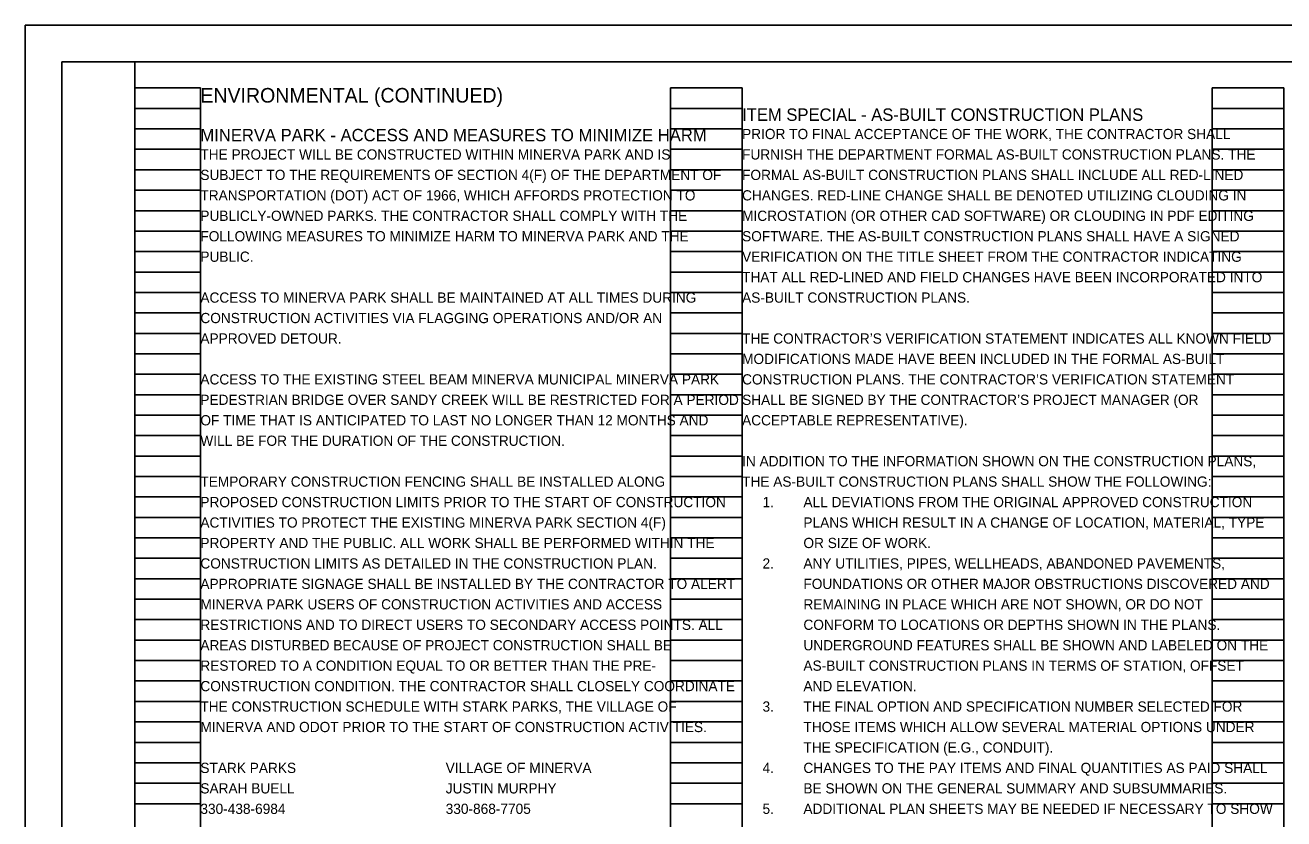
# Model space of a CAD drawing. Extents: x 0 to 34, y 0 to 22.
# Drawn here: x 0 to 17.24, y 11.13 to 22 of the extents above; entities that cross this region are included whole.
import ezdxf

# ---------------------------------------------------------------- set-up
doc = ezdxf.new("R2010")
doc.units = 0
for name, color, linetype in [('SH_Border', 7, 'Continuous'), ('SH_Cut_Line', 7, 'Continuous'), ('SH_Data', 7, 'Continuous'), ('SH_Text', 7, 'Continuous')]:
    doc.layers.add(name, color=color, linetype=linetype)

msp = doc.modelspace()

# ---------------------------------------------------------------- linework, layer by layer
at = {"layer": 'SH_Border'}
for points in [[(0.5, 21.5), (1.5, 21.5), (1.5, 0.5), (0.5, 0.5)], [(1.5, 21.5), (33.5, 21.5), (33.5, 0.5), (1.5, 0.5)]]:
    msp.add_lwpolyline(points, close=True, dxfattribs=at)
at = {"layer": 'SH_Cut_Line'}
msp.add_lwpolyline([(0, 0), (34, 0), (34, 22), (0, 22)], close=True, dxfattribs=at)
at = {"layer": 'SH_Data'}
for p, q in [((1.5, 0.98), (1.5, 21.14)), ((1.5, 21.14), (2.4, 21.14)), ((2.4, 0.98), (2.4, 21.14)), ((8.84, 0.98), (8.84, 21.14)), ((8.84, 21.14), (9.82, 21.14)), ((9.82, 0.98), (9.82, 21.14)), ((16.26, 0.98), (16.26, 21.14)), ((16.26, 21.14), (17.24, 21.14)), ((17.24, 0.98), (17.24, 21.14)), ((1.5, 20.86), (2.4, 20.86)), ((8.84, 20.86), (9.82, 20.86)), ((16.26, 20.86), (17.24, 20.86)), ((1.5, 20.58), (2.4, 20.58)), ((8.84, 20.58), (9.82, 20.58)), ((16.26, 20.58), (17.24, 20.58)), ((1.5, 20.3), (2.4, 20.3)), ((8.84, 20.3), (9.82, 20.3)), ((16.26, 20.3), (17.24, 20.3)), ((1.5, 20.02), (2.4, 20.02)), ((8.84, 20.02), (9.82, 20.02)), ((16.26, 20.02), (17.24, 20.02)), ((1.5, 19.74), (2.4, 19.74)), ((8.84, 19.74), (9.82, 19.74)), ((16.26, 19.74), (17.24, 19.74)), ((1.5, 19.46), (2.4, 19.46)), ((8.84, 19.46), (9.82, 19.46)), ((16.26, 19.46), (17.24, 19.46)), ((1.5, 19.18), (2.4, 19.18)), ((8.84, 19.18), (9.82, 19.18)), ((16.26, 19.18), (17.24, 19.18)), ((1.5, 18.9), (2.4, 18.9)), ((8.84, 18.9), (9.82, 18.9)), ((16.26, 18.9), (17.24, 18.9)), ((1.5, 18.62), (2.4, 18.62)), ((8.84, 18.62), (9.82, 18.62)), ((16.26, 18.62), (17.24, 18.62)), ((1.5, 18.34), (2.4, 18.34)), ((8.84, 18.34), (9.82, 18.34)), ((16.26, 18.34), (17.24, 18.34)), ((1.5, 18.06), (2.4, 18.06)), ((8.84, 18.06), (9.82, 18.06)), ((16.26, 18.06), (17.24, 18.06)), ((1.5, 17.78), (2.4, 17.78)), ((8.84, 17.78), (9.82, 17.78)), ((16.26, 17.78), (17.24, 17.78)), ((1.5, 17.5), (2.4, 17.5)), ((8.84, 17.5), (9.82, 17.5)), ((16.26, 17.5), (17.24, 17.5)), ((1.5, 17.22), (2.4, 17.22)), ((8.84, 17.22), (9.82, 17.22)), ((16.26, 17.22), (17.24, 17.22)), ((1.5, 16.94), (2.4, 16.94)), ((8.84, 16.94), (9.82, 16.94)), ((16.26, 16.94), (17.24, 16.94)), ((1.5, 16.66), (2.4, 16.66)), ((8.84, 16.66), (9.82, 16.66)), ((16.26, 16.66), (17.24, 16.66)), ((1.5, 16.38), (2.4, 16.38)), ((8.84, 16.38), (9.82, 16.38)), ((16.26, 16.38), (17.24, 16.38)), ((1.5, 16.1), (2.4, 16.1)), ((8.84, 16.1), (9.82, 16.1)), ((16.26, 16.1), (17.24, 16.1)), ((1.5, 15.82), (2.4, 15.82)), ((8.84, 15.82), (9.82, 15.82)), ((16.26, 15.82), (17.24, 15.82)), ((1.5, 15.54), (2.4, 15.54)), ((8.84, 15.54), (9.82, 15.54)), ((16.26, 15.54), (17.24, 15.54)), ((1.5, 15.26), (2.4, 15.26)), ((8.84, 15.26), (9.82, 15.26)), ((16.26, 15.26), (17.24, 15.26)), ((1.5, 14.98), (2.4, 14.98)), ((8.84, 14.98), (9.82, 14.98)), ((16.26, 14.98), (17.24, 14.98)), ((1.5, 14.7), (2.4, 14.7)), ((8.84, 14.7), (9.82, 14.7)), ((16.26, 14.7), (17.24, 14.7)), ((1.5, 14.42), (2.4, 14.42)), ((8.84, 14.42), (9.82, 14.42)), ((16.26, 14.42), (17.24, 14.42)), ((1.5, 14.14), (2.4, 14.14)), ((8.84, 14.14), (9.82, 14.14)), ((16.26, 14.14), (17.24, 14.14)), ((1.5, 13.86), (2.4, 13.86)), ((8.84, 13.86), (9.82, 13.86)), ((16.26, 13.86), (17.24, 13.86)), ((1.5, 13.58), (2.4, 13.58)), ((8.84, 13.58), (9.82, 13.58)), ((16.26, 13.58), (17.24, 13.58)), ((1.5, 13.3), (2.4, 13.3)), ((8.84, 13.3), (9.82, 13.3)), ((16.26, 13.3), (17.24, 13.3)), ((1.5, 13.02), (2.4, 13.02)), ((8.84, 13.02), (9.82, 13.02)), ((16.26, 13.02), (17.24, 13.02)), ((1.5, 12.74), (2.4, 12.74)), ((8.84, 12.74), (9.82, 12.74)), ((16.26, 12.74), (17.24, 12.74)), ((1.5, 12.46), (2.4, 12.46)), ((8.84, 12.46), (9.82, 12.46)), ((16.26, 12.46), (17.24, 12.46)), ((1.5, 12.18), (2.4, 12.18)), ((8.84, 12.18), (9.82, 12.18)), ((16.26, 12.18), (17.24, 12.18)), ((1.5, 11.9), (2.4, 11.9)), ((8.84, 11.9), (9.82, 11.9)), ((16.26, 11.9), (17.24, 11.9)), ((1.5, 11.62), (2.4, 11.62)), ((8.84, 11.62), (9.82, 11.62)), ((16.26, 11.62), (17.24, 11.62)), ((1.5, 11.34), (2.4, 11.34)), ((8.84, 11.34), (9.82, 11.34)), ((16.26, 11.34), (17.24, 11.34))]:
    msp.add_line(p, q, dxfattribs=at)

# ---------------------------------------------------------------- texts
at = {"layer": 'SH_Text'}
for s, height, p in [('ENVIRONMENTAL (CONTINUED)', 0.2, (2.4, 20.94)), ('ITEM SPECIAL - AS-BUILT CONSTRUCTION PLANS', 0.17, (9.82, 20.69)), ('MINERVA PARK - ACCESS AND MEASURES TO MINIMIZE HARM', 0.17, (2.4, 20.41)), ('PRIOR TO FINAL ACCEPTANCE OF THE WORK, THE CONTRACTOR SHALL ', 0.14, (9.82, 20.44)), ('THE PROJECT WILL BE CONSTRUCTED WITHIN MINERVA PARK AND IS ', 0.14, (2.4, 20.16)), ('FURNISH THE DEPARTMENT FORMAL AS-BUILT CONSTRUCTION PLANS. THE ', 0.14, (9.82, 20.16)), ('SUBJECT TO THE REQUIREMENTS OF SECTION 4(F) OF THE DEPARTMENT OF ', 0.14, (2.4, 19.88)), ('FORMAL AS-BUILT CONSTRUCTION PLANS SHALL INCLUDE ALL RED-LINED ', 0.14, (9.82, 19.88)), ('TRANSPORTATION (DOT) ACT OF 1966, WHICH AFFORDS PROTECTION TO ', 0.14, (2.4, 19.6)), ('CHANGES. RED-LINE CHANGE SHALL BE DENOTED UTILIZING CLOUDING IN ', 0.14, (9.82, 19.6)), ('PUBLICLY-OWNED PARKS. THE CONTRACTOR SHALL COMPLY WITH THE ', 0.14, (2.4, 19.32)), ('MICROSTATION (OR OTHER CAD SOFTWARE) OR CLOUDING IN PDF EDITING ', 0.14, (9.82, 19.32)), ('FOLLOWING MEASURES TO MINIMIZE HARM TO MINERVA PARK AND THE ', 0.14, (2.4, 19.04)), ('SOFTWARE. THE AS-BUILT CONSTRUCTION PLANS SHALL HAVE A SIGNED ', 0.14, (9.82, 19.04)), ('PUBLIC.', 0.14, (2.4, 18.76)), ('VERIFICATION ON THE TITLE SHEET FROM THE CONTRACTOR INDICATING ', 0.14, (9.82, 18.76)), ('THAT ALL RED-LINED AND FIELD CHANGES HAVE BEEN INCORPORATED INTO ', 0.14, (9.82, 18.48)), ('ACCESS TO MINERVA PARK SHALL BE MAINTAINED AT ALL TIMES DURING ', 0.14, (2.4, 18.2)), ('AS-BUILT CONSTRUCTION PLANS. ', 0.14, (9.82, 18.2)), ('CONSTRUCTION ACTIVITIES VIA FLAGGING OPERATIONS AND/OR AN ', 0.14, (2.4, 17.92)), ('APPROVED DETOUR. ', 0.14, (2.4, 17.64)), ('THE CONTRACTOR’S VERIFICATION STATEMENT INDICATES ALL KNOWN FIELD ', 0.14, (9.82, 17.64)), ('MODIFICATIONS MADE HAVE BEEN INCLUDED IN THE FORMAL AS-BUILT ', 0.14, (9.82, 17.36)), ('ACCESS TO THE EXISTING STEEL BEAM MINERVA MUNICIPAL MINERVA PARK ', 0.14, (2.4, 17.08)), ('CONSTRUCTION PLANS. THE CONTRACTOR’S VERIFICATION STATEMENT ', 0.14, (9.82, 17.08)), ('PEDESTRIAN BRIDGE OVER SANDY CREEK WILL BE RESTRICTED FOR A PERIOD ', 0.14, (2.4, 16.8)), ('SHALL BE SIGNED BY THE CONTRACTOR’S PROJECT MANAGER (OR ', 0.14, (9.82, 16.8)), ('OF TIME THAT IS ANTICIPATED TO LAST NO LONGER THAN 12 MONTHS AND ', 0.14, (2.4, 16.52)), ('ACCEPTABLE REPRESENTATIVE). ', 0.14, (9.82, 16.52)), ('WILL BE FOR THE DURATION OF THE CONSTRUCTION.', 0.14, (2.4, 16.24)), ('IN ADDITION TO THE INFORMATION SHOWN ON THE CONSTRUCTION PLANS, ', 0.14, (9.82, 15.96)), ('TEMPORARY CONSTRUCTION FENCING SHALL BE INSTALLED ALONG ', 0.14, (2.4, 15.68)), ('THE AS-BUILT CONSTRUCTION PLANS SHALL SHOW THE FOLLOWING:', 0.14, (9.82, 15.68)), ('PROPOSED CONSTRUCTION LIMITS PRIOR TO THE START OF CONSTRUCTION ', 0.14, (2.4, 15.4)), ('1.', 0.14, (10.1, 15.4)), ('ALL DEVIATIONS FROM THE ORIGINAL APPROVED CONSTRUCTION ', 0.14, (10.66, 15.4)), ('ACTIVITIES TO PROTECT THE EXISTING MINERVA PARK SECTION 4(F) ', 0.14, (2.4, 15.12)), ('PLANS WHICH RESULT IN A CHANGE OF LOCATION, MATERIAL, TYPE ', 0.14, (10.66, 15.12)), ('PROPERTY AND THE PUBLIC. ALL WORK SHALL BE PERFORMED WITHIN THE ', 0.14, (2.4, 14.84)), ('OR SIZE OF WORK. ', 0.14, (10.66, 14.84)), ('CONSTRUCTION LIMITS AS DETAILED IN THE CONSTRUCTION PLAN. ', 0.14, (2.4, 14.56)), ('2.', 0.14, (10.1, 14.56)), ('ANY UTILITIES, PIPES, WELLHEADS, ABANDONED PAVEMENTS, ', 0.14, (10.66, 14.56)), ('APPROPRIATE SIGNAGE SHALL BE INSTALLED BY THE CONTRACTOR TO ALERT ', 0.14, (2.4, 14.28)), ('FOUNDATIONS OR OTHER MAJOR OBSTRUCTIONS DISCOVERED AND ', 0.14, (10.66, 14.28)), ('MINERVA PARK USERS OF CONSTRUCTION ACTIVITIES AND ACCESS ', 0.14, (2.4, 14)), ('REMAINING IN PLACE WHICH ARE NOT SHOWN, OR DO NOT ', 0.14, (10.66, 14)), ('RESTRICTIONS AND TO DIRECT USERS TO SECONDARY ACCESS POINTS. ALL ', 0.14, (2.4, 13.72)), ('CONFORM TO LOCATIONS OR DEPTHS SHOWN IN THE PLANS. ', 0.14, (10.66, 13.72)), ('AREAS DISTURBED BECAUSE OF PROJECT CONSTRUCTION SHALL BE ', 0.14, (2.4, 13.44)), ('UNDERGROUND FEATURES SHALL BE SHOWN AND LABELED ON THE ', 0.14, (10.66, 13.44)), ('RESTORED TO A CONDITION EQUAL TO OR BETTER THAN THE PRE-', 0.14, (2.4, 13.16)), ('AS-BUILT CONSTRUCTION PLANS IN TERMS OF STATION, OFFSET ', 0.14, (10.66, 13.16)), ('CONSTRUCTION CONDITION. THE CONTRACTOR SHALL CLOSELY COORDINATE ', 0.14, (2.4, 12.88)), ('AND ELEVATION. ', 0.14, (10.66, 12.88)), ('THE CONSTRUCTION SCHEDULE WITH STARK PARKS, THE VILLAGE OF ', 0.14, (2.4, 12.6)), ('3.', 0.14, (10.1, 12.6)), ('THE FINAL OPTION AND SPECIFICATION NUMBER SELECTED FOR ', 0.14, (10.66, 12.6)), ('MINERVA AND ODOT PRIOR TO THE START OF CONSTRUCTION ACTIVITIES.', 0.14, (2.4, 12.32)), ('THOSE ITEMS WHICH ALLOW SEVERAL MATERIAL OPTIONS UNDER ', 0.14, (10.66, 12.32)), ('THE SPECIFICATION (E.G., CONDUIT). ', 0.14, (10.66, 12.04)), ('STARK PARKS', 0.14, (2.4, 11.76)), ('VILLAGE OF MINERVA', 0.14, (5.76, 11.76)), ('4.', 0.14, (10.1, 11.76)), ('CHANGES TO THE PAY ITEMS AND FINAL QUANTITIES AS PAID SHALL ', 0.14, (10.66, 11.76)), ('SARAH BUELL', 0.14, (2.4, 11.48)), ('JUSTIN MURPHY', 0.14, (5.76, 11.48)), ('BE SHOWN ON THE GENERAL SUMMARY AND SUBSUMMARIES. ', 0.14, (10.66, 11.48)), ('330-438-6984', 0.14, (2.4, 11.2)), ('330-868-7705', 0.14, (5.76, 11.2)), ('5.', 0.14, (10.1, 11.2)), ('ADDITIONAL PLAN SHEETS MAY BE NEEDED IF NECESSARY TO SHOW ', 0.14, (10.66, 11.2))]:
    msp.add_text(s, height=height, dxfattribs=at).set_placement(p)

doc.saveas('drawing.dxf')
